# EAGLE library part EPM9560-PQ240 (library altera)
EPM9560 MAX 9000 family
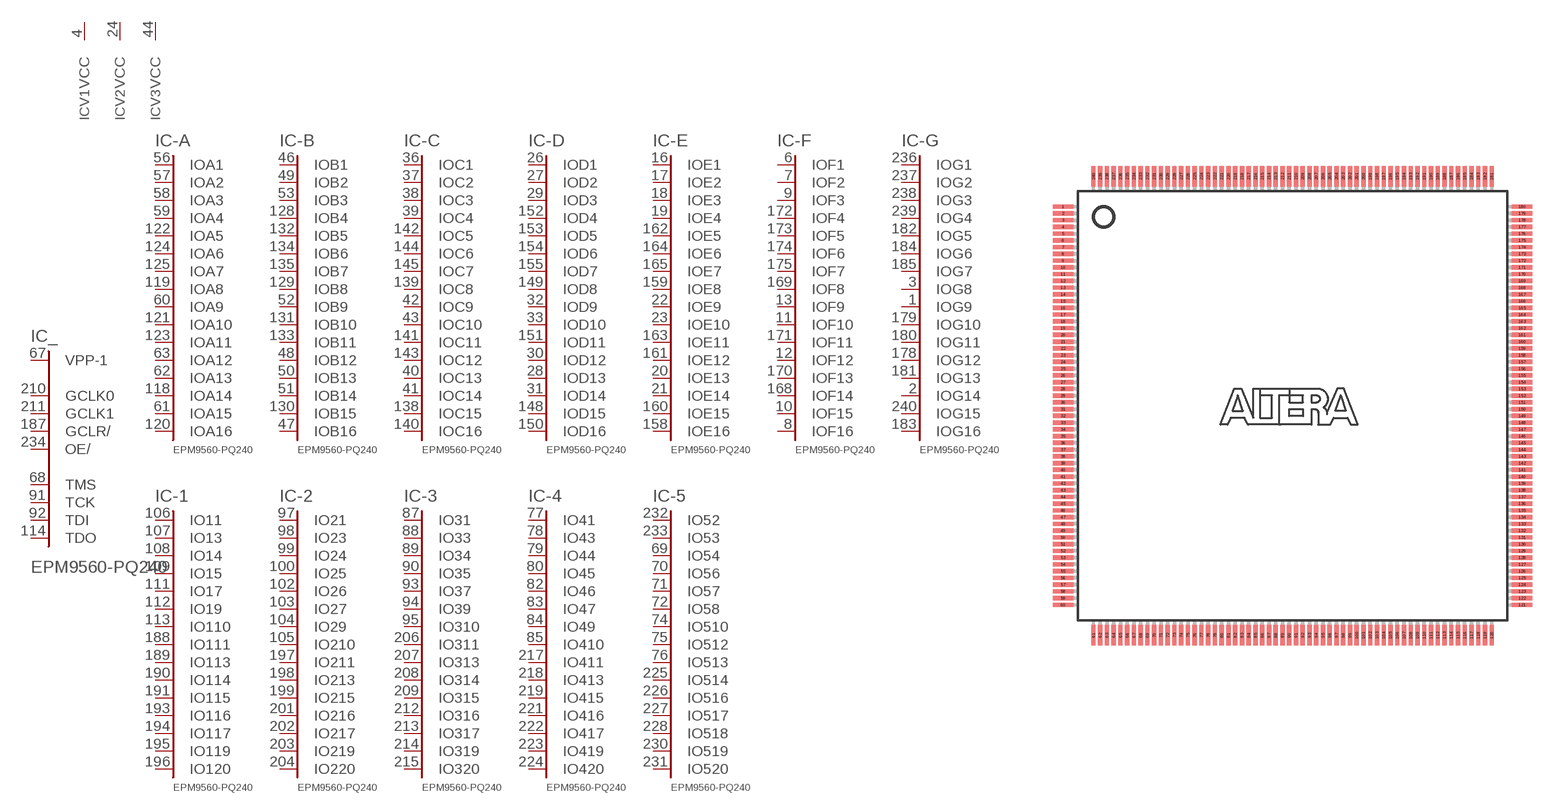
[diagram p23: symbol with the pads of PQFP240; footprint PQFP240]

Designator prefix IC; gates _=9560C356 -A=A16-0 -B=B16-0 -C=C16-0 -D=D16-0 -E=E16-0 -F=F16-0 -G=G16-0 -1=IO120-2 -2=IO220-2 -3=IO320-2 -4=IO420-2 -5=IO520-2 V1=VCCINT V2=VCCINT V3=VCCINT V4=VCCINT V5=VCCINT V6=VCCINT V7=VCCINT V8=VCCINT VO1=VCCIO VO2=VCCIO VO3=VCCIO VO4=VCCIO VO5=VCCIO VO6=VCCIO VO7=VCCIO VO8=VCCIO VO9=VCCIO VO10=VCCIO VO11=VCCIO VO12=VCCIO VO13=VCCIO VO14=VCCIO G1=GND G2=GND G3=GND G4=GND G5=GND G6=GND G7=GND G8=GND G9=GND G10=GND G11=GND G12=GND G13=GND G14=GND G15=GND G16=GND G17=GND G18=GND G19=GND G20=GND G21=GND G22=GND

## EPM9560-PQ240 (MPN: EPM9560ARC240-10; OC_FARNELL: unknown; OC_NEWARK: 51R9963)  [PQFP240]
1  -G:IOG9
2  -G:IOG14
3  -G:IOG8
4  V1:VCC  pwr
5  G1:GND  pwr
6  -F:IOF1
7  -F:IOF2
8  -F:IOF16
9  -F:IOF3
10  -F:IOF15
11  -F:IOF10
12  -F:IOF12
13  -F:IOF9
14  G2:GND  pwr
15  VO1:VCCIO  pwr
16  -E:IOE1
17  -E:IOE2
18  -E:IOE3
19  -E:IOE4
20  -E:IOE13
21  -E:IOE14
22  -E:IOE9
23  -E:IOE10
24  V2:VCC  pwr
25  G3:GND  pwr
26  -D:IOD1
27  -D:IOD2
28  -D:IOD13
29  -D:IOD3
30  -D:IOD12
31  -D:IOD14
32  -D:IOD9
33  -D:IOD10
34  G4:GND  pwr
35  VO2:VCCIO  pwr
36  -C:IOC1
37  -C:IOC2
38  -C:IOC3
39  -C:IOC4
40  -C:IOC13
41  -C:IOC14
42  -C:IOC9
43  -C:IOC10
44  V3:VCC  pwr
45  G5:GND  pwr
46  -B:IOB1
47  -B:IOB16
48  -B:IOB12
49  -B:IOB2
50  -B:IOB13
51  -B:IOB14
52  -B:IOB9
53  -B:IOB3
54  G6:GND  pwr
55  VO3:VCCIO  pwr
56  -A:IOA1
57  -A:IOA2
58  -A:IOA3
59  -A:IOA4
60  -A:IOA9
61  -A:IOA15
62  -A:IOA13
63  -A:IOA12
64  V4:VCC  pwr
65  G7:GND  pwr
66  G8:GND  pwr
67  _:VPP-1  in
68  _:TMS
69  -5:IO54
70  -5:IO56
71  -5:IO57
72  -5:IO58
73  VO4:VCCIO  pwr
74  -5:IO510
75  -5:IO512
76  -5:IO513
77  -4:IO41
78  -4:IO43
79  -4:IO44
80  -4:IO45
81  G9:GND  pwr
82  -4:IO46
83  -4:IO47
84  -4:IO49
85  -4:IO410
86  VO5:VCCIO  pwr
87  -3:IO31
88  -3:IO33
89  -3:IO34
90  -3:IO35
91  _:TCK
92  _:TDI
93  -3:IO37
94  -3:IO39
95  -3:IO310
96  G10:GND  pwr
97  -2:IO21
98  -2:IO23
99  -2:IO24
100  -2:IO25
101  VO6:VCCIO  pwr
102  -2:IO26
103  -2:IO27
104  -2:IO29
105  -2:IO210
106  -1:IO11
107  -1:IO13
108  -1:IO14
109  -1:IO15
110  G11:GND  pwr
111  -1:IO17
112  -1:IO19
113  -1:IO110
114  _:TDO
115  G12:GND  pwr
116  VO7:VCCIO  pwr
117  V5:VCC  pwr
118  -A:IOA14
119  -A:IOA8
120  -A:IOA16
121  -A:IOA10
122  -A:IOA5
123  -A:IOA11
124  -A:IOA6
125  -A:IOA7
126  G13:GND  pwr
127  G14:GND  pwr
128  -B:IOB4
129  -B:IOB8
130  -B:IOB15
131  -B:IOB10
132  -B:IOB5
133  -B:IOB11
134  -B:IOB6
135  -B:IOB7
136  VO8:VCCIO  pwr
137  V6:VCC  pwr
138  -C:IOC15
139  -C:IOC8
140  -C:IOC16
141  -C:IOC11
142  -C:IOC5
143  -C:IOC12
144  -C:IOC6
145  -C:IOC7
146  G15:GND  pwr
147  G16:GND  pwr
148  -D:IOD15
149  -D:IOD8
150  -D:IOD16
151  -D:IOD11
152  -D:IOD4
153  -D:IOD5
154  -D:IOD6
155  -D:IOD7
156  VO9:VCCIO  pwr
157  V7:VCC  pwr
158  -E:IOE16
159  -E:IOE8
160  -E:IOE15
161  -E:IOE12
162  -E:IOE5
163  -E:IOE11
164  -E:IOE6
165  -E:IOE7
166  G17:GND  pwr
167  G18:GND  pwr
168  -F:IOF14
169  -F:IOF8
170  -F:IOF13
171  -F:IOF11
172  -F:IOF4
173  -F:IOF5
174  -F:IOF6
175  -F:IOF7
176  VO10:VCCIO  pwr
177  V8:VCC  pwr
178  -G:IOG12
179  -G:IOG10
180  -G:IOG11
181  -G:IOG13
182  -G:IOG5
183  -G:IOG16
184  -G:IOG6
185  -G:IOG7
186  G19:GND  pwr
187  _:GCLR/  in
188  -1:IO111
189  -1:IO113
190  -1:IO114
191  -1:IO115
192  VO11:VCCIO  pwr
193  -1:IO116
194  -1:IO117
195  -1:IO119
196  -1:IO120
197  -2:IO211
198  -2:IO213
199  -2:IO215
200  G20:GND  pwr
201  -2:IO216
202  -2:IO217
203  -2:IO219
204  -2:IO220
205  VO12:VCCIO  pwr
206  -3:IO311
207  -3:IO313
208  -3:IO314
209  -3:IO315
210  _:GCLK0  in
211  _:GCLK1  in
212  -3:IO316
213  -3:IO317
214  -3:IO319
215  -3:IO320
216  G21:GND  pwr
217  -4:IO411
218  -4:IO413
219  -4:IO415
220  VO13:VCCIO  pwr
221  -4:IO416
222  -4:IO417
223  -4:IO419
224  -4:IO420
225  -5:IO514
226  -5:IO516
227  -5:IO517
228  -5:IO518
229  G22:GND  pwr
230  -5:IO519
231  -5:IO520
232  -5:IO52
233  -5:IO53
234  _:OE/  in
235  VO14:VCCIO  pwr
236  -G:IOG1
237  -G:IOG2
238  -G:IOG3
239  -G:IOG4
240  -G:IOG15

## Footprint PQFP240 (pad centres in mm)
Plastic Quad Flat Pack
smd 1.5 x 0.32: 1 -17,14.75; 2 -17,14.25; 3 -17,13.75; 4 -17,13.25; 5 -17,12.75; 6 -17,12.25; 7 -17,11.75; 8 -17,11.25; 9 -17,10.75; 10 -17,10.25; 11 -17,9.75; 12 -17,9.25; 13 -17,8.75; 14 -17,8.25; 15 -17,7.75; 16 -17,7.25; 17 -17,6.75; 18 -17,6.25; 19 -17,5.75; 20 -17,5.25; 21 -17,4.75; 22 -17,4.25; 23 -17,3.75; 24 -17,3.25; 25 -17,2.75; 26 -17,2.25; 27 -17,1.75; 28 -17,1.25; 29 -17,0.75; 30 -17,0.25; 31 -17,-0.25; 32 -17,-0.75; 33 -17,-1.25; 34 -17,-1.75; 35 -17,-2.25; 36 -17,-2.75; 37 -17,-3.25; 38 -17,-3.75; 39 -17,-4.25; 40 -17,-4.75; 41 -17,-5.25; 42 -17,-5.75; 43 -17,-6.25; 44 -17,-6.75; 45 -17,-7.25; 46 -17,-7.75; 47 -17,-8.25; 48 -17,-8.75; 49 -17,-9.25; 50 -17,-9.75; 51 -17,-10.25; 52 -17,-10.75; 53 -17,-11.25; 54 -17,-11.75; 55 -17,-12.25; 56 -17,-12.75; 57 -17,-13.25; 58 -17,-13.75; 59 -17,-14.25; 60 -17,-14.75; 121 17,-14.75; 122 17,-14.25; 123 17,-13.75; 124 17,-13.25; 125 17,-12.75; 126 17,-12.25; 127 17,-11.75; 128 17,-11.25; 129 17,-10.75; 130 17,-10.25; 131 17,-9.75; 132 17,-9.25; 133 17,-8.75; 134 17,-8.25; 135 17,-7.75; 136 17,-7.25; 137 17,-6.75; 138 17,-6.25; 139 17,-5.75; 140 17,-5.25; 141 17,-4.75; 142 17,-4.25; 143 17,-3.75; 144 17,-3.25; 145 17,-2.75; 146 17,-2.25; 147 17,-1.75; 148 17,-1.25; 149 17,-0.75; 150 17,-0.25; 151 17,0.25; 152 17,0.75; 153 17,1.25; 154 17,1.75; 155 17,2.25; 156 17,2.75; 157 17,3.25; 158 17,3.75; 159 17,4.25; 160 17,4.75; 161 17,5.25; 162 17,5.75; 163 17,6.25; 164 17,6.75; 165 17,7.25; 166 17,7.75; 167 17,8.25; 168 17,8.75; 169 17,9.25; 170 17,9.75; 171 17,10.25; 172 17,10.75; 173 17,11.25; 174 17,11.75; 175 17,12.25; 176 17,12.75; 177 17,13.25; 178 17,13.75; 179 17,14.25; 180 17,14.75
smd 0.32 x 1.5: 61 -14.75,-17; 62 -14.25,-17; 63 -13.75,-17; 64 -13.25,-17; 65 -12.75,-17; 66 -12.25,-17; 67 -11.75,-17; 68 -11.25,-17; 69 -10.75,-17; 70 -10.25,-17; 71 -9.75,-17; 72 -9.25,-17; 73 -8.75,-17; 74 -8.25,-17; 75 -7.75,-17; 76 -7.25,-17; 77 -6.75,-17; 78 -6.25,-17; 79 -5.75,-17; 80 -5.25,-17; 81 -4.75,-17; 82 -4.25,-17; 83 -3.75,-17; 84 -3.25,-17; 85 -2.75,-17; 86 -2.25,-17; 87 -1.75,-17; 88 -1.25,-17; 89 -0.75,-17; 90 -0.25,-17; 91 0.25,-17; 92 0.75,-17; 93 1.25,-17; 94 1.75,-17; 95 2.25,-17; 96 2.75,-17; 97 3.25,-17; 98 3.75,-17; 99 4.25,-17; 100 4.75,-17; 101 5.25,-17; 102 5.75,-17; 103 6.25,-17; 104 6.75,-17; 105 7.25,-17; 106 7.75,-17; 107 8.25,-17; 108 8.75,-17; 109 9.25,-17; 110 9.75,-17; 111 10.25,-17; 112 10.75,-17; 113 11.25,-17; 114 11.75,-17; 115 12.25,-17; 116 12.75,-17; 117 13.25,-17; 118 13.75,-17; 119 14.25,-17; 120 14.75,-17; 181 14.75,17; 182 14.25,17; 183 13.75,17; 184 13.25,17; 185 12.75,17; 186 12.25,17; 187 11.75,17; 188 11.25,17; 189 10.75,17; 190 10.25,17; 191 9.75,17; 192 9.25,17; 193 8.75,17; 194 8.25,17; 195 7.75,17; 196 7.25,17; 197 6.75,17; 198 6.25,17; 199 5.75,17; 200 5.25,17; 201 4.75,17; 202 4.25,17; 203 3.75,17; 204 3.25,17; 205 2.75,17; 206 2.25,17; 207 1.75,17; 208 1.25,17; 209 0.75,17; 210 0.25,17; 211 -0.25,17; 212 -0.75,17; 213 -1.25,17; 214 -1.75,17; 215 -2.25,17; 216 -2.75,17; 217 -3.25,17; 218 -3.75,17; 219 -4.25,17; 220 -4.75,17; 221 -5.25,17; 222 -5.75,17; 223 -6.25,17; 224 -6.75,17; 225 -7.25,17; 226 -7.75,17; 227 -8.25,17; 228 -8.75,17; 229 -9.25,17; 230 -9.75,17; 231 -10.25,17; 232 -10.75,17; 233 -11.25,17; 234 -11.75,17; 235 -12.25,17; 236 -12.75,17; 237 -13.25,17; 238 -13.75,17; 239 -14.25,17; 240 -14.75,17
